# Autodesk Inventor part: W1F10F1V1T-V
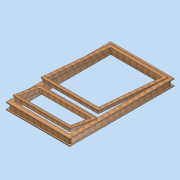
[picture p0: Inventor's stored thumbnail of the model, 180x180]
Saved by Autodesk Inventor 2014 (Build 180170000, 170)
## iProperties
Created: 2011-04
Part Number: W1F10F1V1T-V
Document SubType Name: Modeling
Designer: david.appleford
Density: 0.746522 g/cm^3
Description: Window 900 x 1500 Type A 1 Panel
Mass: 26000 g
Surface Area: 28996.6 cm^2
Volume: 34828.2 cm^3
Cost Center: £350.00
Material: 000 Redwood
Appearance: Wood (Oak)
Justset: False
Author: david.appleford
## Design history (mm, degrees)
sketch "Sketch1"
  geometry: L1 (466, 857)-(466, -643); L2 (466, -643)-(-434, -643); L3 (-434, -643)-(-434, 857); L4 (-434, 857)-(466, 857); L5 (592, 1202)-(592, -1170); L6 (-560, 1202)-(592, 1202); L7 (-560, -1170)-(-560, 1202); L8 (592, -1170)-(-560, -1170); L9 (481, 872)-(481, -658); L10 (481, -658)-(-449, -658); L11 (-449, -658)-(-449, 872); L12 (-449, 872)-(481, 872); L13 (422, 813)-(422, -599); L14 (422, -599)-(-390, -599); L15 (-390, -599)-(-390, 813); L16 (-390, 813)-(422, 813); 1 further point
  constraints: 32 end point, 6 other
  dimensions: "d0" = 15 distance between parallel lines of L4 L12; "d1" = 44 distance between parallel lines of L15 L3; "d31" = 345 distance between parallel lines of L6 L4; "d32" = 2372 distance between parallel lines of L6 L8; "d33" = 1152 distance between parallel lines of L5 L7; "d34" = 900 distance between parallel lines of L1 L3; "d35" = 126 distance between parallel lines of L3 L7 (= -0.5 x d34 + 0.5 x d33); "d36" = 1500 distance between parallel lines of L4 L2
extrude "Extrusion1" new body sketch "Sketch1" distance "d2" = 12; taper "d3" = 0 deg
workplane "Work Plane1"
sketch "Sketch2"
  geometry: L1 (-481, 872)-(-481, -658) reference; L2 (449, 872)-(-481, 872) reference; L3 (449, -658)-(449, 872) reference; L4 (-481, -658)-(449, -658) reference; L5 (-422, -599)-(-422, 813) reference; L6 (-422, 813)-(390, 813) reference; L7 (390, 813)-(390, -599) reference; L8 (390, -599)-(-422, -599) reference; 1 further point
extrude "Extrusion2" join sketch "Sketch2" distance "d4" = 12; taper "d5" = 0 deg
sketch "Sketch3"
  geometry: L1 (-422, 813)-(390, 813) reference; L2 (-422, -599)-(-422, 813) reference; L3 (390, -599)-(-422, -599) reference; L4 (390, 813)-(390, -599) reference; L5 (434, 857)-(434, -643); L6 (-466, 857)-(434, 857); L7 (-466, -643)-(-466, 857); L8 (434, -643)-(-466, -643); L9 (-481, 872)-(-481, -658) reference; L10 (-481, -658)-(449, -658) reference; L11 (449, 872)-(-481, 872) reference; 1 further point
  constraints: 8 end point
  dimensions: "d37" = 900 distance between parallel lines of L7 L5; "d38" = 15 distance between parallel lines of L9 L7; "d39" = 15 distance between parallel lines of L8 L10 (= d38); "d40" = 15 distance between parallel lines of L11 L6 (= d38)
workplane "Work Plane2"
extrude "Extrusion3" join sketch "Sketch3" stored distance "d6" = 12; taper "d7" = 0 deg
sketch "Sketch5"
  geometry: L1 (0, -59)-(0, 1471) reference; L2 (-12, 1471)-(0, 1471) reference; L3 (-12, -59)-(-12, 1471) reference; L4 (-12, -59)-(0, -59) reference; L5 (0, 1412)-(-104, 1412) reference; L6 (0, 1427.057)-(89.335, 405.958); L7 (1.307, 1412.114)-(-42.525, 1408.28); L8 (-42.525, 1408.28)-(44.195, 417.066); L9 (44.195, 417.066)-(88.027, 420.901); L10 (0, 1427.057)-(11.954, 1428.103); L11 (11.954, 1428.103)-(101.289, 407.004); L12 (101.289, 407.004)-(89.335, 405.958)
  constraints: 14 end point, 4 perpendicular, 3 point on line, 2 parallel
  dimensions: "d13" = 15 distance from line of L7 L6.start; "d15" = 995 distance between parallel lines of L9 L7; "d16" = 15 distance from line of L6.end L9; "d17" = 12 distance between parallel lines of L6 L11; "d18" = 44 distance between parallel lines of L8 L6; "d41" = 5 deg angle of L1 L6
extrude "Extrusion5" join sketch "Sketch5" stored distance "d19" = 10; taper "d20" = 0 deg
sketch "Sketch6"
  geometry: L1 (812, 0)-(812, 12) reference; L2 (812, 12)-(827, 12); L3 (827, 12)-(827, 0); L4 (827, 0)-(812, 0); L5 (812, 0)-(812, 12); L6 (0, 12)-(0, 0) reference; L7 (0, 12)-(-15, 12); L8 (-15, 12)-(-15, 0); L9 (-15, 0)-(0, 0); L10 (0, 0)-(0, 12); L11 (812, 0)-(0, 0) reference; 1 further point
  constraints: 16 end point, 4 parallel, 2 collinear, 2 horizontal, 2 perpendicular
  dimensions: "d21" = 15 distance between parallel lines of L8 L10; "d22" = 15 distance between parallel lines of L3 L1
extrude "Extrusion6" join sketch "Sketch6" stored distance "d23" = 10; taper "d24" = 0 deg
sketch "Sketch7"
  geometry: L1 (812, -995)-(812, -487.922) reference; L2 (812, 0)-(812, -487.922) reference; L3 (0, 0)-(812, 0) reference; L4 (0, -487.922)-(0, 0) reference; L5 (0, -487.922)-(0, -995) reference; L6 (0, -995)-(812, -995) reference; L7 (783, -29)-(783, -966); L8 (783, -966)-(29, -966); L9 (29, -966)-(29, -217.639); L10 (29, -217.639)-(29, -29); L11 (29, -29)-(783, -29); L12 (-15, -1010)-(-15, 15) reference; L13 (827, -1010)-(827, 15) reference; 1 further point
  constraints: 10 end point, 3 other
  dimensions: "d25" = 44 distance between parallel lines of L10 L12; "d42" = 44 distance between parallel lines of L13 L7 (= d25)
extrude "Extrusion7" cut sketch "Sketch7" stored distance "d26" = 10; taper "d27" = 0 deg
chamfer "Chamfer1" distance "d28" = 20; stored, may be unused: second distance "d29" = 2, angle "d30" = 45 deg
sketch "Sketch8"
  geometry: L1 (-104, 0)-(-104, 922.214) reference; L2 (-104, 412)-(-60, 412); L3 (-60, 412)-(-60, 368); L4 (-60, 368)-(-104, 368); L5 (-104, 368)-(-104, 412); L6 (0, 1412)-(-104, 1412) reference; 1 further point
  constraints: 8 end point, 1 point on line
  dimensions: "d43" = 44 distance between parallel lines of L4 L2; "d44" = 44 distance between parallel lines of L3 L5; "d45" = 1000 distance between parallel lines of L2 L6
extrude "Extrusion8" join sketch "Sketch8" stored distance "d46" = 10; taper "d47" = 0 deg
sketch "Sketch9" dims "d39" = 15 (= d38)
  geometry: L1 (104, -59)-(104, 1471) reference; L2 (60, 368)-(104, 368) reference; L3 (106.605, 368.459)-(63.273, 360.819); L4 (63.273, 360.819)-(126.655, 1.364); L5 (126.655, 1.364)-(169.986, 9.004); L6 (104, 383.231)-(115.818, 385.315); L7 (115.818, 385.315)-(184.409, -3.684); L8 (184.409, -3.684)-(172.591, -5.768); L9 (104, 383.231)-(106.605, 368.459); L10 (169.986, 9.004)-(172.591, -5.768); 1 further point
  constraints: 16 end point, 4 perpendicular, 2 point on line, 1 collinear
  dimensions: "d48" = 15 distance from line of L6.start L3; "d51" = 15 distance between parallel lines of L8 L5 (= d48); "d52" = 365 distance between parallel lines of L5 L3; "d54" = 44 distance between parallel lines of L10 L4; "d55" = 12 distance between parallel lines of L7 L10; "d56" = 10 deg angle of L7 L1
extrude "Extrusion9" join sketch "Sketch9" stored distance "d57" = 10; taper "d58" = 0 deg
sketch "Sketch10"
  geometry: L1 (0, 12)-(0, 0) reference; L2 (812, 0)-(0, 0) reference; L3 (812, 12)-(812, 0) reference; L4 (812, 12)-(0, 12) reference; L5 (0, 12)-(-15, 12); L6 (-15, 12)-(-15, 0); L7 (-15, 0)-(0, 0); L8 (0, 0)-(0, 12); L9 (812, 12)-(827, 12); L10 (827, 12)-(827, 0); L11 (827, 0)-(812, 0); L12 (812, 0)-(812, 12); 1 further point
  constraints: 16 end point
  dimensions: "d59" = 15 distance between parallel lines of L8 L6; "d60" = 15 distance between parallel lines of L10 L12 (= d59)
extrude "Extrusion10" join sketch "Sketch10" stored distance "d61" = 10; taper "d62" = 0 deg
sketch "Sketch11"
  geometry: L1 (0, 0)-(842, 0) reference; L2 (842, 0)-(842, 395) reference; L3 (842, 395)-(0, 395) reference; L4 (0, 0)-(0, 395) reference; L5 (44, 351)-(798, 351); L6 (798, 351)-(798, 44); L7 (798, 44)-(44, 44); L8 (44, 44)-(44, 351); 1 further point
  constraints: 8 end point, 3 other
  dimensions: "d63" = 44 distance between parallel lines of L5 L3
extrude "Extrusion11" cut sketch "Sketch11" stored distance "d64" = 10; taper "d65" = 0 deg
body "Solid1"
node "Projected Loop1"
node "Projected Loop2"
node "Projected Loop3"
node "Projected Loop4"
feature "쁘"
feature "쀀䁃"
feature "䀀쁙"
other parameters: "d49" = 44, "d50" = 12, "d53" = 10 deg
